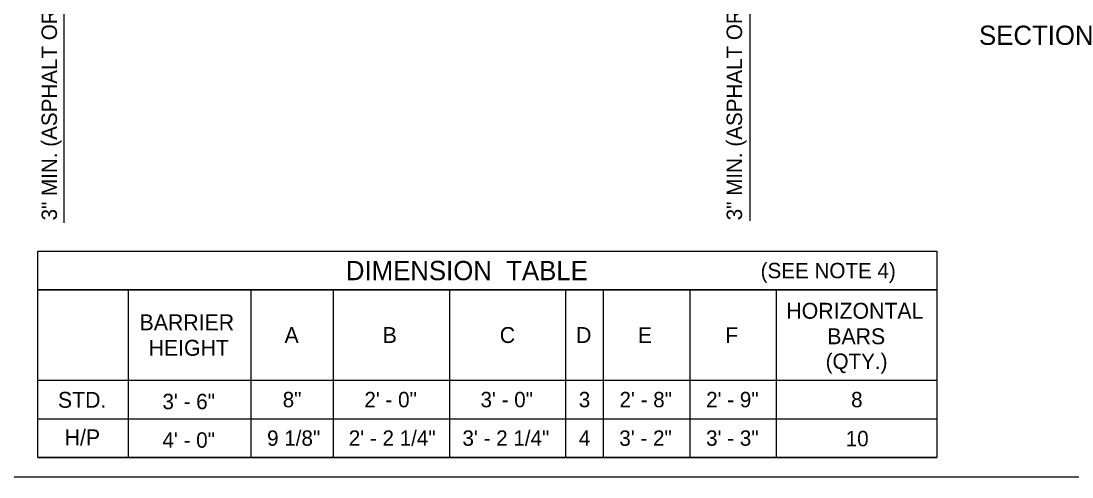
# Model space of a CAD drawing. Extents: x 99862 to 103151, y 100000 to 102076.
# Drawn here: x 100719 to 101810, y 100000 to 100473 of the extents above; entities that cross this region are included whole.
import ezdxf

# ---------------------------------------------------------------- set-up
doc = ezdxf.new("R2010")
doc.units = 0
for name, color, linetype in [('Level 1', 7, 'Continuous'), ('Level 15', 7, 'Continuous'), ('Level 20', 7, 'Continuous'), ('Level 40', 7, 'Continuous')]:
    doc.layers.add(name, color=color, linetype=linetype)

msp = doc.modelspace()

# ---------------------------------------------------------------- linework, layer by layer
at = {"layer": 'Level 1'}
msp.add_lwpolyline([(99862, 99999.5), (103151, 99999.5), (103151, 102075.5), (99862, 102075.5)], close=True, dxfattribs=at)
at = {"layer": 'Level 15'}
for p, q in [((100763.6, 100263.5), (100763.6, 100652)), ((101475.8, 100265.6), (101475.8, 100652))]:
    msp.add_line(p, q, dxfattribs=at)
at = {"layer": 'Level 40'}
for p, q in [((100830.1, 100193.9), (100830.1, 100019.9)), ((100957.4, 100193.9), (100957.4, 100019.9)), ((101043.1, 100193.9), (101043.1, 100019.9)), ((101163.6, 100193.9), (101163.6, 100019.9)), ((101284, 100193.9), (101284, 100019.9)), ((101323.2, 100193.9), (101323.2, 100019.9)), ((101413.1, 100193.9), (101413.1, 100019.9)), ((101502.9, 100193.9), (101502.9, 100019.9)), ((100736.4, 100099.9), (101669.7, 100099.9)), ((100736.4, 100059.9), (101669.7, 100059.9)), ((100736.4, 100019.9), (101669.7, 100019.9))]:
    msp.add_line(p, q, dxfattribs=at)
for points in [[(100736.4, 100233.9), (101669.7, 100233.9), (101669.7, 100193.9), (100736.4, 100193.9)], [(100736.4, 100193.9), (101669.7, 100193.9), (101669.7, 100019.9), (100736.4, 100019.9)]]:
    msp.add_lwpolyline(points, close=True, dxfattribs=at)

# ---------------------------------------------------------------- texts
at = {"layer": 'Level 15'}
for s, p in [('HORIZONTAL', (101513.4, 100163.9)), ('BARRIER', (100842.1, 100151.9)), ('A', (100992.5, 100138.7)), ('B', (101094.4, 100138.7)), ('C', (101215.9, 100138.7)), ('D', (101295.1, 100138.7)), ('E', (101359.3, 100138.6)), ('F', (101449.9, 100138.6)), ('BARS', (101555.9, 100137.4)), ('HEIGHT', (100851.4, 100125.4))]:
    msp.add_text(s, height=16.5, dxfattribs=at).set_placement(p)
at = {"layer": 'Level 20'}
for p in [(100756.3, 100266), (101467.4, 100266.1)]:
    msp.add_text('3" MIN. (ASPHALT OR CONCRETE)', height=16, rotation=90, dxfattribs=at).set_placement(p)
for s, height, p in [('SECTION', 20, (101713.4, 100448.3)), ('DIMENSION  TABLE', 20, (101056.2, 100203.9)), ('(SEE NOTE 4)', 16, (101486.7, 100205.9)), ('(QTY.)', 16, (101554.2, 100111.7)), ('STD.', 16.5, (100757.3, 100071.4)), ('3\' - 6"', 16, (100865.8, 100069.9)), ('8"', 16, (100990.6, 100071.9)), ('2\' - 0"', 16, (101075.4, 100071.9)), ('3\' - 0"', 16, (101195.9, 100071.9)), ('3', 16, (101297.9, 100071.9)), ('2\' - 8"', 16, (101340.2, 100071.9)), ('2\' - 9"', 16, (101430.1, 100071.9)), ('8', 16, (101580.6, 100071.9)), ('H/P', 16.5, (100764.3, 100032.4)), ('4\' - 0"', 16, (100865.8, 100029.9)), ('9 1/8"', 16, (100974.4, 100031.9)), ('2\' - 2 1/4"', 16, (101059.2, 100031.9)), ('3\' - 2 1/4"', 16, (101177.2, 100031.9)), ('4', 16, (101297.9, 100031.9)), ('3\' - 2"', 16, (101340, 100031.9)), ('3\' - 3"', 16, (101430.1, 100031.9)), ('10', 16, (101575, 100031.4))]:
    msp.add_text(s, height=height, dxfattribs=at).set_placement(p)

doc.saveas('drawing.dxf')
